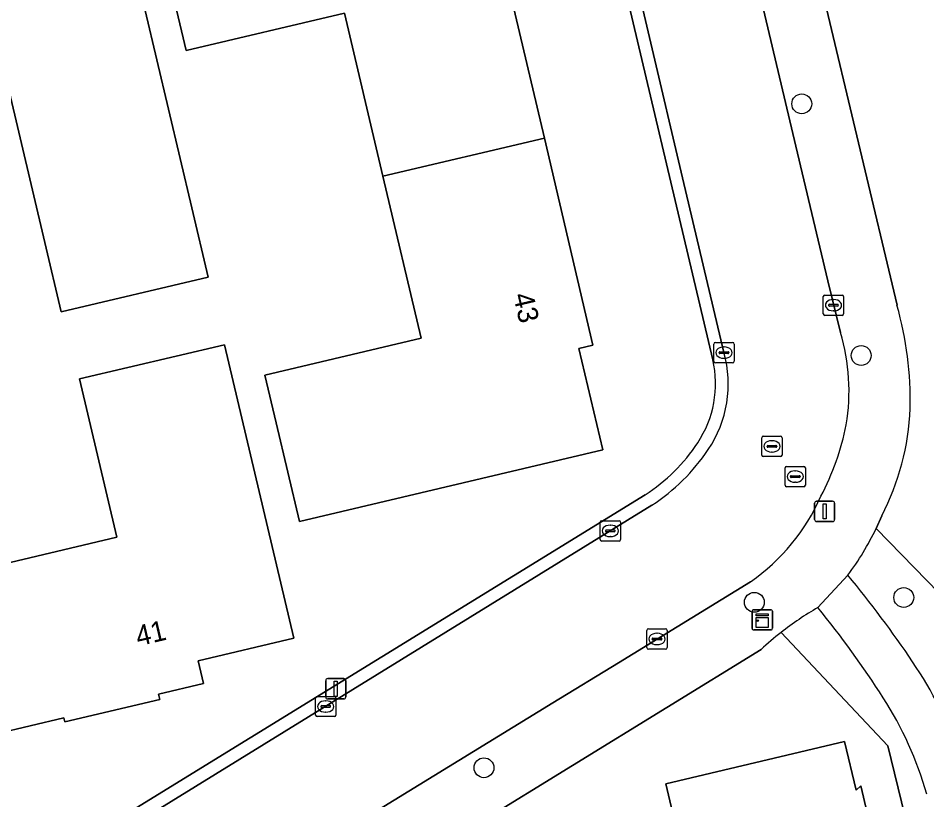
# Model space of a CAD drawing. Extents: x 157648 to 158502, y 379212 to 380938.
# Drawn here: x 158282.88 to 158327.67, y 380551.53 to 380590.04 of the extents above; entities that cross this region are included whole.
import ezdxf

# ---------------------------------------------------------------- set-up
doc = ezdxf.new("R2010")
doc.units = 0
for name, color, linetype in [('IMGEO_Boom', 7, 'Continuous'), ('IMGEO_Erf', 7, 'Continuous'), ('IMGEO_Groenvoorziening', 7, 'Continuous'), ('IMGEO_Kast', 7, 'Continuous'), ('IMGEO_Kolk', 7, 'Continuous'), ('IMGEO_Lichtmast', 7, 'Continuous'), ('IMGEO_Pand', 7, 'Continuous'), ('IMGEO_Pand_nummerreeks', 7, 'Continuous'), ('IMGEO_Rijbaan_lokaal_open', 7, 'Continuous'), ('IMGEO_Rioolput', 7, 'Continuous'), ('IMGEO_Voetpad_open', 7, 'Continuous')]:
    doc.layers.add(name, color=color, linetype=linetype)

msp = doc.modelspace()

# ---------------------------------------------------------------- linework, layer by layer
at = {"layer": 'IMGEO_Boom'}
for centre in [(158321.505, 380585.823), (158324.432, 380573.421), (158319.167, 380561.261), (158326.532, 380561.497), (158305.842, 380553.107)]:
    msp.add_circle(centre, 0.489, dxfattribs=at)
at = {"layer": 'IMGEO_Erf'}
for points in [[(158290.496, 380609.857), (158307.597, 380613.868), (158305.939, 380620.881), (158306.328, 380620.973), (158305.772, 380623.305), (158320.313, 380626.756), (158323.196, 380614.738), (158324.911, 380607.502), (158326.647, 380600.235), (158320.737, 380598.882), (158326.199, 380575.894)], [(158317.125, 380573.209), (158311.984, 380594.967)], [(158279.84, 380562.604), (158287.75, 380564.472), (158285.909, 380572.269), (158293.053, 380573.955), (158296.468, 380559.488), (158291.752, 380558.375), (158292.016, 380557.255), (158289.804, 380556.733), (158289.865, 380556.476), (158285.18, 380555.37), (158285.132, 380555.571), (158281.797, 380554.784)], [(158255.365, 380530.629), (158313.789, 380566.552)], [(158325.445, 380565.516), (158325.171, 380564.899), (158330.152, 380559.787)], [(158319.496, 380558.936), (158263.701, 380524.634), (158257.585, 380520.788), (158257.469, 380520.719), (158257.353, 380520.65), (158261.062, 380505.621), (158262.697, 380504.321), (158264.187, 380502.857), (158265.516, 380501.245), (158266.367, 380500), (158267.425, 380498.089), (158268.197, 380496.241), (158268.772, 380494.324), (158269.143, 380492.356), (158269.406, 380490.783), (158269.906, 380488.917), (158270.597, 380487.114), (158271.474, 380485.392), (158272.525, 380483.772), (158289.215, 380500), (158329.422, 380539.101), (158325.742, 380554.195), (158320.483, 380559.775)], [(158315.614, 380548.904), (158314.809, 380552.314), (158323.618, 380554.394), (158324.184, 380551.998), (158324.409, 380552.21), (158325.283, 380548.506)]]:
    msp.add_lwpolyline(points, dxfattribs=at)
for points in [[(158290.624, 380590.742), (158289.475, 380595.608), (158304.376, 380599.126), (158305.555, 380594.129), (158306.205, 380594.282), (158306.511, 380592.984), (158306.727, 380593.035), (158308.819, 380584.132), (158311.215, 380573.937), (158310.521, 380573.774), (158311.701, 380568.774), (158296.746, 380565.243), (158295.597, 380570.11), (158295.044, 380572.45), (158302.748, 380574.269), (158300.861, 380582.262), (158298.966, 380590.29), (158291.165, 380588.448)], [(158284.202, 380578.996), (158282.375, 380586.733), (158274.437, 380584.859), (158272.544, 380592.878), (158280.783, 380594.822), (158280.817, 380594.677), (158283.016, 380595.196), (158283.254, 380594.187), (158287.998, 380595.307), (158291.445, 380580.706), (158292.253, 380577.282), (158285.011, 380575.572)]]:
    msp.add_lwpolyline(points, close=True, dxfattribs=at)
for centre, radius, start, end in [((158309.481, 380571.159), 17.375, 358.8263, 15.8142), ((158311.981, 380572.04), 5.275, 326.463, 12.8014), ((158314.119, 380571.363), 12.746, 332.6943, 357.4807), ((158308.821, 380574.138), 9.069, 303.2211, 326.446), ((158330.045, 380547.527), 15.538, 127.9772, 132.7552)]:
    msp.add_arc(centre, radius, start, end, dxfattribs=at)
at = {"layer": 'IMGEO_Groenvoorziening'}
for points in [[(158330.152, 380559.787), (158325.171, 380564.899)], [(158320.483, 380559.775), (158325.742, 380554.195), (158329.422, 380539.101), (158334.137, 380543.912)]]:
    msp.add_lwpolyline(points, dxfattribs=at)
for centre, radius, start, end in [((158313.306, 380570.536), 13.137, 322.8277, 334.5877), ((158282.918, 380528.699), 53.088, 33.9223, 39.6844), ((158330.179, 380547.353), 15.759, 120.0004, 127.9743), ((158286.976, 380532.068), 45.66, 32.4322, 39.3184), ((158311.395, 380547.703), 18.853, 18.4588, 34.2964), ((158310.761, 380547.001), 17.577, 15.8582, 32.9298)]:
    msp.add_arc(centre, radius, start, end, dxfattribs=at)
at = {"layer": 'IMGEO_Kast'}
for p, q in [((158319.058, 380559.97), (158319.058, 380560.811)), ((158319.058, 380560.811), (158319.058, 380559.97)), ((158319.133, 380560.895), (158319.974, 380560.895)), ((158319.974, 380560.895), (158319.133, 380560.895)), ((158320.058, 380560.82), (158320.058, 380559.979)), ((158320.058, 380559.979), (158320.058, 380560.82)), ((158319.983, 380559.895), (158319.142, 380559.895)), ((158319.142, 380559.895), (158319.983, 380559.895))]:
    msp.add_line(p, q, dxfattribs=at)
for points in [[(158319.253, 380560.685), (158319.853, 380560.685), (158319.853, 380560.6), (158319.253, 380560.6), (158319.253, 380560.685)], [(158319.253, 380560.51), (158319.853, 380560.51), (158319.853, 380560.021), (158319.253, 380560.021), (158319.253, 380560.51)]]:
    msp.add_lwpolyline(points, dxfattribs=at)
msp.add_circle((158319.337, 380560.359), 0.0377, dxfattribs=at)
for centre, start, end in [((158319.136, 380560.817), 92.4484, 184.2845), ((158319.136, 380560.817), 92.4484, 184.2845), ((158319.98, 380560.817), 2.4484, 94.2845), ((158319.98, 380560.817), 2.4484, 94.2845), ((158319.136, 380559.973), 182.4484, 274.2845), ((158319.136, 380559.973), 182.4484, 274.2845), ((158319.98, 380559.973), 272.4484, 4.2845), ((158319.98, 380559.973), 272.4484, 4.2845)]:
    msp.add_arc(centre, 0.0779, start, end, dxfattribs=at)
at = {"layer": 'IMGEO_Kolk'}
for p, q in [((158322.567, 380575.475), (158322.567, 380576.327)), ((158322.642, 380576.401), (158323.494, 380576.401)), ((158323.055, 380576.181), (158323.08, 380576.181)), ((158323.568, 380576.327), (158323.568, 380575.475)), ((158322.826, 380575.895), (158322.826, 380575.907)), ((158323.264, 380575.858), (158322.866, 380575.858)), ((158322.869, 380575.944), (158323.267, 380575.944)), ((158323.078, 380575.621), (158323.053, 380575.621)), ((158323.31, 380575.907), (158323.31, 380575.895)), ((158323.494, 380575.401), (158322.642, 380575.401)), ((158317.171, 380573.136), (158317.171, 380573.988)), ((158317.246, 380574.062), (158318.098, 380574.062)), ((158317.659, 380573.842), (158317.684, 380573.842)), ((158318.172, 380573.988), (158318.172, 380573.136)), ((158317.43, 380573.556), (158317.43, 380573.568)), ((158317.868, 380573.519), (158317.47, 380573.519)), ((158317.473, 380573.605), (158317.871, 380573.605)), ((158317.914, 380573.568), (158317.914, 380573.556)), ((158318.098, 380573.062), (158317.246, 380573.062)), ((158317.682, 380573.282), (158317.657, 380573.282)), ((158311.645, 380565.28), (158312.497, 380565.28)), ((158311.57, 380564.354), (158311.57, 380565.206)), ((158311.872, 380564.823), (158312.27, 380564.823)), ((158312.058, 380565.06), (158312.083, 380565.06)), ((158312.571, 380565.206), (158312.571, 380564.354)), ((158311.829, 380564.774), (158311.829, 380564.786)), ((158312.267, 380564.737), (158311.869, 380564.737)), ((158312.081, 380564.5), (158312.056, 380564.5)), ((158312.313, 380564.786), (158312.313, 380564.774)), ((158312.497, 380564.28), (158311.645, 380564.28)), ((158313.945, 380559.952), (158314.797, 380559.952)), ((158313.87, 380559.026), (158313.87, 380559.878)), ((158314.129, 380559.446), (158314.129, 380559.458)), ((158314.172, 380559.495), (158314.57, 380559.495)), ((158314.358, 380559.732), (158314.383, 380559.732)), ((158314.613, 380559.458), (158314.613, 380559.446)), ((158314.871, 380559.878), (158314.871, 380559.026)), ((158314.567, 380559.409), (158314.169, 380559.409)), ((158314.381, 380559.172), (158314.356, 380559.172)), ((158314.797, 380558.952), (158313.945, 380558.952)), ((158297.542, 380555.699), (158297.542, 380556.551)), ((158297.617, 380556.625), (158298.469, 380556.625)), ((158298.03, 380556.405), (158298.055, 380556.405)), ((158298.543, 380556.551), (158298.543, 380555.699)), ((158297.801, 380556.119), (158297.801, 380556.131)), ((158298.239, 380556.082), (158297.841, 380556.082)), ((158297.844, 380556.168), (158298.242, 380556.168)), ((158298.285, 380556.131), (158298.285, 380556.119)), ((158298.469, 380555.625), (158297.617, 380555.625)), ((158298.053, 380555.845), (158298.028, 380555.845))]:
    msp.add_line(p, q, dxfattribs=at)
for points in [[(158322.567, 380575.475), (158322.567, 380576.327)], [(158322.642, 380576.401), (158323.494, 380576.401)], [(158323.568, 380576.327), (158323.568, 380575.475)], [(158323.494, 380575.401), (158322.642, 380575.401)], [(158317.171, 380573.136), (158317.171, 380573.988)], [(158317.246, 380574.062), (158318.098, 380574.062)], [(158318.172, 380573.988), (158318.172, 380573.136)], [(158318.098, 380573.062), (158317.246, 380573.062)], [(158311.645, 380565.28), (158312.497, 380565.28)], [(158311.57, 380564.354), (158311.57, 380565.206)], [(158312.571, 380565.206), (158312.571, 380564.354)], [(158312.497, 380564.28), (158311.645, 380564.28)], [(158313.945, 380559.952), (158314.797, 380559.952)], [(158313.87, 380559.026), (158313.87, 380559.878)], [(158314.871, 380559.878), (158314.871, 380559.026)], [(158314.797, 380558.952), (158313.945, 380558.952)], [(158297.542, 380555.699), (158297.542, 380556.551)], [(158297.617, 380556.625), (158298.469, 380556.625)], [(158298.543, 380556.551), (158298.543, 380555.699)], [(158298.469, 380555.625), (158297.617, 380555.625)]]:
    msp.add_lwpolyline(points, dxfattribs=at)
for centre, radius, start, end in [((158322.644, 380576.325), 0.0765, 91.552, 178.448), ((158322.644, 380576.325), 0.0765, 91.552, 178.448), ((158323.492, 380576.325), 0.0765, 1.552, 88.448), ((158323.492, 380576.325), 0.0765, 1.552, 88.448), ((158322.866, 380575.904), 0.0403, 85.8775, 175.7526), ((158322.863, 380575.894), 0.0366, 178.938, 274.7102), ((158323.267, 380575.901), 0.043, 264.8664, 352.4533), ((158323.271, 380575.906), 0.0386, 1.7309, 96.639), ((158322.644, 380575.477), 0.0765, 181.552, 268.448), ((158322.644, 380575.477), 0.0765, 181.552, 268.448), ((158323.492, 380575.477), 0.0765, 271.552, 358.448), ((158323.492, 380575.477), 0.0765, 271.552, 358.448), ((158317.248, 380573.986), 0.0765, 91.552, 178.448), ((158317.248, 380573.986), 0.0765, 91.552, 178.448), ((158318.096, 380573.986), 0.0765, 1.552, 88.448), ((158318.096, 380573.986), 0.0765, 1.552, 88.448), ((158317.47, 380573.565), 0.0403, 85.8775, 175.7526), ((158317.467, 380573.555), 0.0366, 178.938, 274.7102), ((158317.871, 380573.562), 0.043, 264.8664, 352.4533), ((158317.875, 380573.567), 0.0386, 1.7309, 96.639), ((158317.248, 380573.138), 0.0765, 181.552, 268.448), ((158317.248, 380573.138), 0.0765, 181.552, 268.448), ((158318.096, 380573.138), 0.0765, 271.552, 358.448), ((158318.096, 380573.138), 0.0765, 271.552, 358.448), ((158311.647, 380565.204), 0.0765, 91.552, 178.448), ((158311.647, 380565.204), 0.0765, 91.552, 178.448), ((158312.495, 380565.204), 0.0765, 1.552, 88.448), ((158312.495, 380565.204), 0.0765, 1.552, 88.448), ((158311.869, 380564.783), 0.0403, 85.8775, 175.7526), ((158312.274, 380564.785), 0.0386, 1.7309, 96.639), ((158311.866, 380564.773), 0.0366, 178.938, 274.7102), ((158312.27, 380564.78), 0.043, 264.8664, 352.4533), ((158311.647, 380564.356), 0.0765, 181.552, 268.448), ((158311.647, 380564.356), 0.0765, 181.552, 268.448), ((158312.495, 380564.356), 0.0765, 271.552, 358.448), ((158312.495, 380564.356), 0.0765, 271.552, 358.448), ((158313.947, 380559.876), 0.0765, 91.552, 178.448), ((158313.947, 380559.876), 0.0765, 91.552, 178.448), ((158314.795, 380559.876), 0.0765, 1.552, 88.448), ((158314.795, 380559.876), 0.0765, 1.552, 88.448), ((158314.169, 380559.455), 0.0403, 85.8775, 175.7526), ((158314.166, 380559.445), 0.0366, 178.938, 274.7102), ((158314.57, 380559.452), 0.043, 264.8664, 352.4533), ((158314.574, 380559.457), 0.0386, 1.7309, 96.639), ((158313.947, 380559.028), 0.0765, 181.552, 268.448), ((158313.947, 380559.028), 0.0765, 181.552, 268.448), ((158314.795, 380559.028), 0.0765, 271.552, 358.448), ((158314.795, 380559.028), 0.0765, 271.552, 358.448), ((158297.619, 380556.549), 0.0765, 91.552, 178.448), ((158297.619, 380556.549), 0.0765, 91.552, 178.448), ((158298.467, 380556.549), 0.0765, 1.552, 88.448), ((158298.467, 380556.549), 0.0765, 1.552, 88.448), ((158297.841, 380556.128), 0.0403, 85.8775, 175.7526), ((158297.838, 380556.118), 0.0366, 178.938, 274.7102), ((158298.242, 380556.125), 0.043, 264.8664, 352.4533), ((158298.246, 380556.13), 0.0386, 1.7309, 96.639), ((158297.619, 380555.701), 0.0765, 181.552, 268.448), ((158297.619, 380555.701), 0.0765, 181.552, 268.448), ((158298.467, 380555.701), 0.0765, 271.552, 358.448), ((158298.467, 380555.701), 0.0765, 271.552, 358.448)]:
    msp.add_arc(centre, radius, start, end, dxfattribs=at)
for centre, major_axis, ratio, start_param, end_param in [((158323.054, 380575.901), (-0.387, 0.002), 0.722429, 4.712389, 7.853982), ((158323.079, 380575.901), (-0.39, 0.002), 0.717154, 1.570796, 4.712389), ((158317.658, 380573.562), (-0.387, 0.002), 0.722429, 4.712389, 7.853982), ((158317.683, 380573.562), (-0.39, 0.002), 0.717154, 1.570796, 4.712389), ((158312.057, 380564.78), (-0.387, 0.002), 0.722429, 4.712389, 7.853982), ((158312.082, 380564.78), (-0.39, 0.002), 0.717154, 1.570796, 4.712389), ((158314.357, 380559.452), (-0.387, 0.002), 0.722429, 4.712389, 7.853982), ((158314.382, 380559.452), (-0.39, 0.002), 0.717154, 1.570796, 4.712389), ((158298.029, 380556.125), (-0.387, 0.002), 0.722429, 4.712389, 7.853982), ((158298.054, 380556.125), (-0.39, 0.002), 0.717154, 1.570796, 4.712389)]:
    msp.add_ellipse(centre, major_axis=major_axis, ratio=ratio, start_param=start_param, end_param=end_param, dxfattribs=at)
at = {"layer": 'IMGEO_Lichtmast'}
for p, q in [((158322.234, 380566.24), (158323.024, 380566.24)), ((158323.024, 380566.24), (158322.234, 380566.24)), ((158322.134, 380565.34), (158322.134, 380566.14)), ((158322.134, 380566.14), (158322.134, 380565.34)), ((158323.124, 380566.14), (158323.124, 380565.34)), ((158323.124, 380565.34), (158323.124, 380566.14)), ((158323.024, 380565.24), (158322.234, 380565.24)), ((158322.234, 380565.24), (158323.024, 380565.24)), ((158298.041, 380556.598), (158298.041, 380557.398)), ((158298.041, 380557.398), (158298.041, 380556.598)), ((158298.141, 380557.498), (158298.931, 380557.498)), ((158298.931, 380557.498), (158298.141, 380557.498)), ((158299.031, 380557.398), (158299.031, 380556.598)), ((158299.031, 380556.598), (158299.031, 380557.398)), ((158298.931, 380556.498), (158298.141, 380556.498)), ((158298.141, 380556.498), (158298.931, 380556.498))]:
    msp.add_line(p, q, dxfattribs=at)
for points in [[(158322.554, 380566.115), (158322.704, 380566.115), (158322.704, 380565.365), (158322.554, 380565.365), (158322.554, 380566.115)], [(158298.461, 380557.373), (158298.611, 380557.373), (158298.611, 380556.623), (158298.461, 380556.623), (158298.461, 380557.373)]]:
    msp.add_lwpolyline(points, dxfattribs=at)
for centre, start, end in [((158322.234, 380566.14), 90, 180), ((158322.234, 380566.14), 90, 180), ((158323.024, 380566.14), 0, 90), ((158323.024, 380566.14), 360, 90), ((158322.234, 380565.34), 180, 270), ((158322.234, 380565.34), 180, 270), ((158323.024, 380565.34), 270, 0), ((158323.024, 380565.34), 270, 0), ((158298.141, 380557.398), 90, 180), ((158298.141, 380557.398), 90, 180), ((158298.931, 380557.398), 0, 90), ((158298.931, 380557.398), 360, 90), ((158298.141, 380556.598), 180, 270), ((158298.141, 380556.598), 180, 270), ((158298.931, 380556.598), 270, 0), ((158298.931, 380556.598), 270, 0)]:
    msp.add_arc(centre, 0.1, start, end, dxfattribs=at)
at = {"layer": 'IMGEO_Pand'}
for points in [[(158308.819, 380584.132), (158306.727, 380593.035), (158306.511, 380592.984), (158306.205, 380594.282), (158305.555, 380594.129), (158304.376, 380599.126), (158289.475, 380595.608), (158290.624, 380590.742), (158291.165, 380588.448), (158298.966, 380590.29), (158300.861, 380582.262)], [(158287.998, 380595.307), (158283.254, 380594.187), (158283.016, 380595.196), (158280.817, 380594.677), (158280.783, 380594.822), (158272.544, 380592.878), (158274.437, 380584.859), (158282.375, 380586.733), (158284.202, 380578.996), (158285.011, 380575.572), (158292.253, 380577.282), (158291.445, 380580.706)], [(158308.819, 380584.132), (158300.861, 380582.262), (158302.748, 380574.269), (158295.044, 380572.45), (158295.597, 380570.11), (158296.746, 380565.243), (158311.701, 380568.774), (158310.521, 380573.774), (158311.215, 380573.937)], [(158281.797, 380554.784), (158285.132, 380555.571), (158285.18, 380555.37), (158289.865, 380556.476), (158289.804, 380556.733), (158292.016, 380557.255), (158291.752, 380558.375), (158296.468, 380559.488), (158293.053, 380573.955), (158285.909, 380572.269), (158287.75, 380564.472), (158279.84, 380562.604), (158281.69, 380554.759)], [(158311.024, 380546.579), (158313.014, 380538.151), (158313.099, 380537.792), (158320.226, 380539.474), (158319.072, 380544.361), (158325.728, 380545.932), (158325.129, 380548.469), (158325.283, 380548.506), (158324.409, 380552.21), (158324.184, 380551.998), (158323.618, 380554.394), (158314.809, 380552.314), (158315.614, 380548.904), (158310.747, 380547.756)]]:
    msp.add_lwpolyline(points, close=True, dxfattribs=at)
at = {"layer": 'IMGEO_Rijbaan_lokaal_open'}
for points in [[(158323.422, 380574.556), (158322.791, 380577.099), (158321.209, 380583.738), (158317.867, 380597.905), (158317.627, 380598.927), (158311.698, 380597.277)], [(158312.582, 380595.103), (158314.072, 380588.815), (158315.622, 380582.173), (158317.672, 380573.562)], [(158314.118, 380566.039), (158287.044, 380549.358), (158283.176, 380546.981), (158274.251, 380541.515), (158269.107, 380538.35), (158258.895, 380532.075), (158255.673, 380530.111), (158255.474, 380529.996)], [(158258.475, 380525.117), (158258.671, 380525.235), (158261.874, 380527.217), (158271.47, 380533.125), (158274.688, 380535.092), (158284.111, 380540.882), (158287.327, 380542.854), (158296.248, 380548.339), (158299.467, 380550.309), (158309.243, 380556.306), (158312.474, 380558.276), (158318.985, 380562.272)]]:
    msp.add_lwpolyline(points, dxfattribs=at)
for centre, radius, start, end in [((158313.49, 380571.664), 10.344, 350.7872, 16.2337), ((158312.063, 380572.023), 5.816, 326.2148, 15.3398), ((158310.787, 380572.632), 13.178, 332.2015, 348.5156), ((158308.652, 380574.342), 9.941, 303.3583, 326.0406), ((158313.138, 380570.598), 10.175, 305.0793, 336.1599)]:
    msp.add_arc(centre, radius, start, end, dxfattribs=at)
at = {"layer": 'IMGEO_Rioolput'}
for p, q in [((158319.535, 380568.518), (158319.535, 380569.37)), ((158319.61, 380569.444), (158320.462, 380569.444)), ((158320.536, 380569.37), (158320.536, 380568.518)), ((158319.794, 380568.938), (158319.794, 380568.95)), ((158320.232, 380568.901), (158319.834, 380568.901)), ((158319.837, 380568.987), (158320.235, 380568.987)), ((158320.023, 380569.224), (158320.048, 380569.224)), ((158320.278, 380568.95), (158320.278, 380568.938)), ((158320.462, 380568.444), (158319.61, 380568.444)), ((158320.046, 380568.664), (158320.021, 380568.664)), ((158320.758, 380567.955), (158321.61, 380567.955)), ((158320.683, 380567.029), (158320.683, 380567.881)), ((158321.171, 380567.735), (158321.196, 380567.735)), ((158321.684, 380567.881), (158321.684, 380567.029)), ((158320.942, 380567.449), (158320.942, 380567.461)), ((158321.38, 380567.412), (158320.982, 380567.412)), ((158320.985, 380567.498), (158321.383, 380567.498)), ((158321.194, 380567.175), (158321.169, 380567.175)), ((158321.426, 380567.461), (158321.426, 380567.449)), ((158321.61, 380566.955), (158320.758, 380566.955))]:
    msp.add_line(p, q, dxfattribs=at)
for points in [[(158319.535, 380568.518), (158319.535, 380569.37)], [(158319.61, 380569.444), (158320.462, 380569.444)], [(158320.536, 380569.37), (158320.536, 380568.518)], [(158320.462, 380568.444), (158319.61, 380568.444)], [(158320.758, 380567.955), (158321.61, 380567.955)], [(158320.683, 380567.029), (158320.683, 380567.881)], [(158321.684, 380567.881), (158321.684, 380567.029)], [(158321.61, 380566.955), (158320.758, 380566.955)]]:
    msp.add_lwpolyline(points, dxfattribs=at)
for centre, radius, start, end in [((158319.612, 380569.368), 0.0765, 91.552, 178.448), ((158319.612, 380569.368), 0.0765, 91.552, 178.448), ((158320.46, 380569.368), 0.0765, 1.552, 88.448), ((158320.46, 380569.368), 0.0765, 1.552, 88.448), ((158319.834, 380568.947), 0.0403, 85.8775, 175.7526), ((158319.831, 380568.937), 0.0366, 178.938, 274.7102), ((158320.235, 380568.944), 0.043, 264.8664, 352.4533), ((158320.239, 380568.949), 0.0386, 1.7309, 96.639), ((158319.612, 380568.52), 0.0765, 181.552, 268.448), ((158319.612, 380568.52), 0.0765, 181.552, 268.448), ((158320.46, 380568.52), 0.0765, 271.552, 358.448), ((158320.46, 380568.52), 0.0765, 271.552, 358.448), ((158320.76, 380567.879), 0.0765, 91.552, 178.448), ((158320.76, 380567.879), 0.0765, 91.552, 178.448), ((158321.608, 380567.879), 0.0765, 1.552, 88.448), ((158321.608, 380567.879), 0.0765, 1.552, 88.448), ((158320.982, 380567.458), 0.0403, 85.8775, 175.7526), ((158320.979, 380567.448), 0.0366, 178.938, 274.7102), ((158321.383, 380567.455), 0.043, 264.8664, 352.4533), ((158321.387, 380567.46), 0.0386, 1.7309, 96.639), ((158320.76, 380567.031), 0.0765, 181.552, 268.448), ((158320.76, 380567.031), 0.0765, 181.552, 268.448), ((158321.608, 380567.031), 0.0765, 271.552, 358.448), ((158321.608, 380567.031), 0.0765, 271.552, 358.448)]:
    msp.add_arc(centre, radius, start, end, dxfattribs=at)
for centre, major_axis, ratio, start_param, end_param in [((158320.022, 380568.944), (-0.387, 0.002), 0.722429, 4.712389, 7.853982), ((158320.047, 380568.944), (-0.39, 0.002), 0.717154, 1.570796, 4.712389), ((158321.17, 380567.455), (-0.387, 0.002), 0.722429, 4.712389, 7.853982), ((158321.195, 380567.455), (-0.39, 0.002), 0.717154, 1.570796, 4.712389)]:
    msp.add_ellipse(centre, major_axis=major_axis, ratio=ratio, start_param=start_param, end_param=end_param, dxfattribs=at)
at = {"layer": 'IMGEO_Voetpad_open'}
for points in [[(158326.199, 380575.894), (158320.737, 380598.882), (158326.647, 380600.235), (158324.911, 380607.502), (158323.196, 380614.738), (158320.313, 380626.756), (158305.772, 380623.305), (158306.328, 380620.973), (158308.079, 380613.57), (158290.602, 380609.471)], [(158317.627, 380598.927), (158317.867, 380597.905), (158321.209, 380583.738), (158322.791, 380577.099), (158323.422, 380574.556)], [(158311.984, 380594.967), (158317.125, 380573.209)], [(158317.672, 380573.562), (158315.622, 380582.173), (158314.072, 380588.815), (158312.582, 380595.103)], [(158313.789, 380566.552), (158255.365, 380530.629)], [(158255.474, 380529.996), (158255.673, 380530.111), (158258.895, 380532.075), (158269.107, 380538.35), (158274.251, 380541.515), (158283.176, 380546.981), (158287.044, 380549.358), (158314.118, 380566.039)], [(158325.171, 380564.899), (158325.445, 380565.516)], [(158323.773, 380562.599), (158322.3, 380561)], [(158322.3, 380561), (158323.773, 380562.599)], [(158318.985, 380562.272), (158312.474, 380558.276), (158309.243, 380556.306), (158299.467, 380550.309), (158296.248, 380548.339), (158287.327, 380542.854), (158284.111, 380540.882), (158274.688, 380535.092), (158271.47, 380533.125), (158261.874, 380527.217), (158258.671, 380525.235), (158258.475, 380525.117)], [(158263.701, 380524.634), (158319.496, 380558.936)]]:
    msp.add_lwpolyline(points, dxfattribs=at)
for centre, radius, start, end in [((158309.481, 380571.159), 17.375, 358.8263, 15.8142), ((158313.49, 380571.664), 10.344, 350.7872, 16.2337), ((158312.063, 380572.023), 5.816, 326.2148, 15.3398), ((158311.981, 380572.04), 5.275, 326.463, 12.8014), ((158314.119, 380571.363), 12.746, 332.6943, 357.4807), ((158310.787, 380572.632), 13.178, 332.2015, 348.5156), ((158308.821, 380574.138), 9.069, 303.2211, 326.446), ((158308.652, 380574.342), 9.941, 303.3583, 326.0406), ((158313.138, 380570.598), 10.175, 305.0793, 336.1599), ((158313.306, 380570.536), 13.137, 322.8277, 334.5877), ((158282.918, 380528.699), 53.088, 33.9223, 39.6844), ((158330.179, 380547.353), 15.759, 120.0004, 127.9743), ((158286.976, 380532.068), 45.66, 32.4322, 39.3184), ((158330.045, 380547.527), 15.538, 127.9772, 132.7552), ((158311.395, 380547.703), 18.853, 18.4588, 34.2964), ((158310.761, 380547.001), 17.577, 15.8582, 32.9298)]:
    msp.add_arc(centre, radius, start, end, dxfattribs=at)

# ---------------------------------------------------------------- texts
at = {"layer": 'IMGEO_Pand_nummerreeks'}
for s, rotation, p in [('43', 283.2245, (158307.268, 380576.397)), ('41', 13.2781, (158288.804, 380559.087))]:
    msp.add_text(s, height=1, rotation=rotation, dxfattribs=at).set_placement(p)

doc.saveas('drawing.dxf')
